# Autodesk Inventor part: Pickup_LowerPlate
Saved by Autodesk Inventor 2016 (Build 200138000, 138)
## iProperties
Created: 2016-01
Part Number: Pickup_LowerPlate
Material: Generic
Document SubType Name: Modeling
Designer: Juha-Pekka
Density: 1 g/cm^3
Appearance: Default
Author: Juha-Pekka
Revision Number: ANY
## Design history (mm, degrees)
fillet "Fillet1"
body "Solid1"
